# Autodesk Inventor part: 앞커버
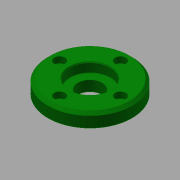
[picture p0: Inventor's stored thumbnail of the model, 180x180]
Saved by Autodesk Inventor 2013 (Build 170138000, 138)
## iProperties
Created: 2015-09
Part Number: 앞커버
Material: 알루미늄 6061
Document SubType Name: Modeling
Designer: mduedu
Density: 1 g/cm^3
Author: mduedu
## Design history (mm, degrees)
sketch "스케치1"
  geometry: L1 (0, 7.5)-(0, -7.5); L2 (0, 7.5)-(31, 7.5); L3 (31, 7.5)-(31, -2.5); L4 (31, -2.5)-(17.5, -2.5); L5 (17.5, -2.5)-(17.5, -7.5); L6 (17.5, -7.5)-(0, -7.5); 2 further points
  constraints: 12 end point, 2 parallel, 2 perpendicular, 1 coincident, 1 horizontal, 1 midpoint, 1 vertical
  dimensions: "d0" = 15 distance of L1.start L1.end; "d1" = 62 diameter of L3 L1; "d2" = 35 diameter of L5 L1; "d3" = 10 distance of L2.end L3.end
revolve "회전1" sketch "스케치1" stored, may be unused: angle "d4" = 90 deg
hole "구멍1" diameter "d7" = 30; stored, may be unused: countersink angle "d11" = 90 deg, drill point angle "d13" = 0 deg; dims "d5" = 10, "d6" = 10, "d8" = 6, "d9" = 4, "d10" = 2, "d12" = 7.3
hole "구멍2" diameter "d16" = 18; stored, may be unused: countersink angle "d20" = 90 deg, drill point angle "d22" = 0 deg; dims "d14" = 10, "d15" = 10, "d17" = 6, "d18" = 4, "d19" = 2, "d21" = 7.3
chamfer "모따기1" distance "d23" = 2; stored, may be unused: second distance "d24" = 2, angle "d25" = 45 deg
chamfer "모따기2" distance "d26" = 0.7; stored, may be unused: second distance "d27" = 2, angle "d28" = 30 deg
fillet "모깎기1" dims "d29" = 0.3
sketch "스케치2" dims "d30" = 45
  geometry: 6 further points
  constraints: 2 vertical alignment, 1 coincident, 7 other
  dimensions: "d34" = 360 deg dimension on point (0, 0) point (0, 22.5) (derived)
sketch "스케치3"
  geometry: 4 further points
hole "구멍3" sketch "스케치3" at (0, 22.5), (-22.5, 0), (22.5, 0), (0, -22.5) diameter "d36" = 4.5; stored, may be unused: countersink angle "d40" = 90 deg, drill point angle "d42" = 0 deg; dims "d37" = 6, "d38" = 8, "d39" = 4.6, "d41" = 8
chamfer "모따기3" distance "d43" = 1; stored, may be unused: second distance "d44" = 2, angle "d45" = 45 deg
node "솔리드1"
